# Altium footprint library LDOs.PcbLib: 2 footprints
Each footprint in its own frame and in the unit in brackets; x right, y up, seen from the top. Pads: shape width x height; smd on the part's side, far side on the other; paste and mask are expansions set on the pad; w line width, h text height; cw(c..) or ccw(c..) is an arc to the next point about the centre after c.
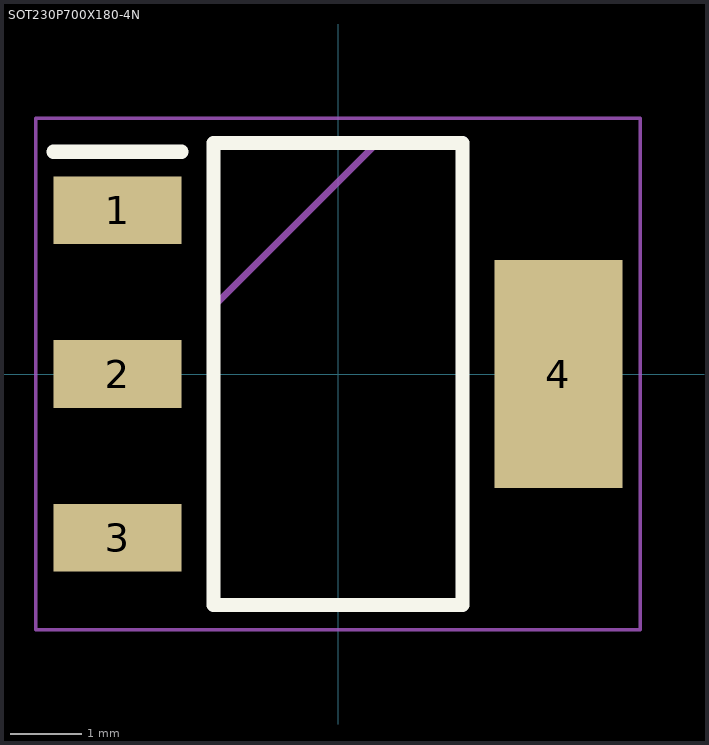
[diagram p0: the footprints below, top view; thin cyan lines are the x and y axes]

## PCBComponent_1 [mm]

## SOT230P700X180-4N [mm]
pads (4):
  rect 1.8x0.95 smd: 1(-3.1,2.3) 2(-3.1,0) 3(-3.1,-2.3)
  rect 1.8x3.2 smd: 4(3.1,0)
Top Overlay:
  lines w0.2: -4,3.125 -2.2,3.125 ; -1.75,-3.25 -1.75,3.25 1.75,3.25 1.75,-3.25 -1.75,-3.25
Mechanical 13:
  lines w0.1: -1.75,0.95 0.55,3.25 ; -1.75,-3.25 -1.75,3.25 1.75,3.25 1.75,-3.25 -1.75,-3.25
Mechanical 15:
  lines w0.05: -4.25,-3.6 -4.25,3.6 4.25,3.6 4.25,-3.6 -4.25,-3.6
3D body "TL1963A-33DCYR.stp": height 1.68, standoff 0, extent -3.5,-3.25 3.5,3.25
